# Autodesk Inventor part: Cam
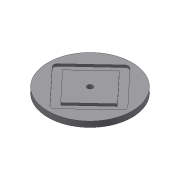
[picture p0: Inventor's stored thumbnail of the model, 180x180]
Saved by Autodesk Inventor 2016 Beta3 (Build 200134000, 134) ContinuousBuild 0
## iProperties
Created: 2016-03
Part Number: Cam
Material: Generic
Document SubType Name: Modeling
Designer: Gaurav
Density: 1 g/cm^3
Appearance: Default
Author: Gaurav
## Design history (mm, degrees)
sketch "Sketch1"
  geometry: C1 r 6 at (0, 0) reference; C2 r 6 at (0, 0); C3 r 90 at (0, 0); 1 further point
  constraints: 2 centre point, 2 coincident, 1 concentric
  dimensions: "d5" = 180 diameter of C3
extrude "Extrusion1" new body sketch "Sketch1" distance "d6" = 12; taper "d7" = 0 deg
sketch "Sketch2"
  geometry: L1 (-77.951, -3.136)-(-8.171, -77.585); L2 (3.136, -77.951)-(77.585, -8.171); L3 (77.951, 3.136)-(8.171, 77.585); L4 (-3.136, 77.951)-(-77.585, 8.171); L5 (-1.968, -60.806)-(-60.806, 1.968); L6 (-60.806, 1.968)-(1.968, 60.806); L7 (1.968, 60.806)-(60.806, -1.968); L8 (60.806, -1.968)-(-1.968, -60.806); C1 r 6 at (0, 0) reference; A1 r 8 centre (-72.114, 2.334) between (-77.585, 8.171) and (-77.951, -3.136); A2 r 8 centre (2.334, 72.114) between (8.171, 77.585) and (-3.136, 77.951); A3 r 8 centre (72.114, -2.334) between (77.585, -8.171) and (77.951, 3.136); A4 r 8 centre (-2.334, -72.114) between (-8.171, -77.585) and (3.136, -77.951); 3 further points
  constraints: 16 end point, 8 point on circle, 8 tangent, 6 point on line, 4 centre point, 3 equal radius, 2 parallel, 2 perpendicular, 3 other
  dimensions: "d15" = 118.038 distance of point (2.7, 83.422) point (-83.422, 2.7); "d16" = 118.038 distance of point (2.7, 83.422) point (83.422, -2.7); "d17" = 8 radius of A1; "d18" = 16 distance between parallel lines of L1 L5
extrude "Extrusion2" cut sketch "Sketch2" distance "d13" = 5; taper "d14" = 0 deg
body "Solid1"
node "Reference1"
